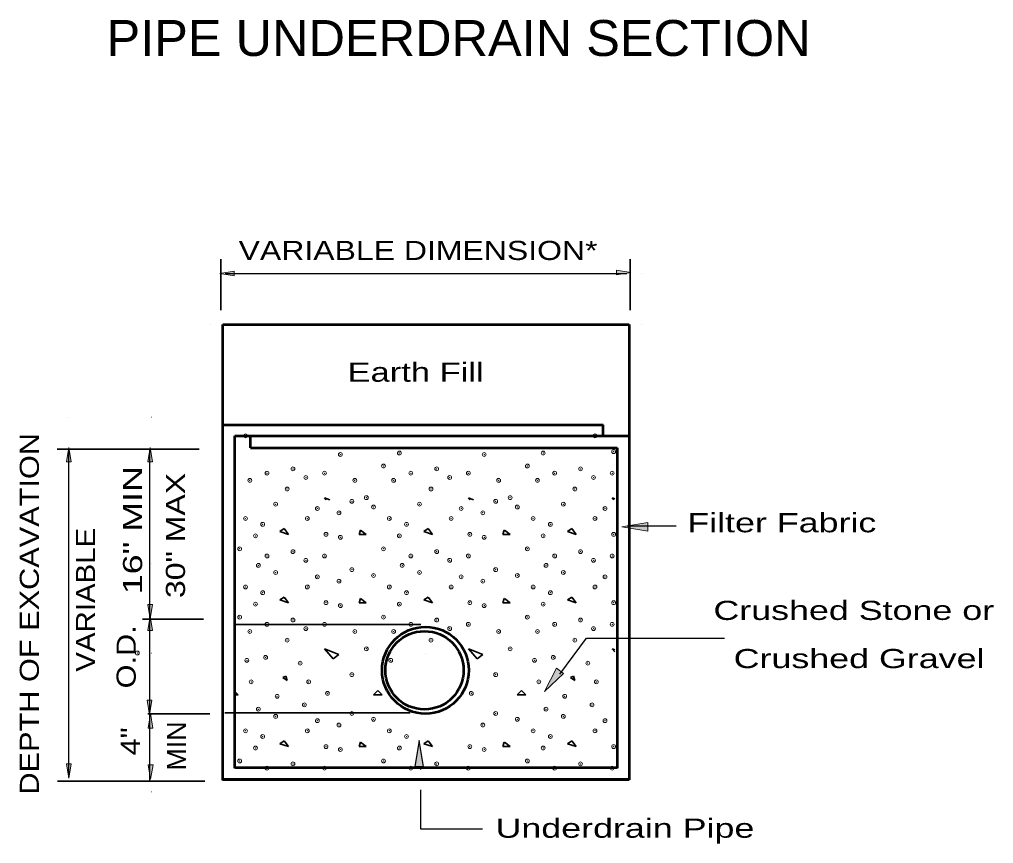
# Model space of a CAD drawing. Extents: x 36 to 71.3, y 0.3 to 22.3.
# Drawn here: x 54.2 to 60.98, y 10.65 to 16.38 of the extents above; entities that cross this region are included whole.
import ezdxf

# ---------------------------------------------------------------- set-up
doc = ezdxf.new("R2010")
doc.units = 0
doc.header["$LTSCALE"] = 0.053
doc.header["$PDMODE"] = 32
doc.header["$PDSIZE"] = 0.0265
for name, color, linetype, lineweight in [('1', 7, 'Continuous', 13), ('2', 7, 'Continuous', 13), ('4', 7, 'Continuous', 13)]:
    doc.layers.add(name, color=color, linetype=linetype, lineweight=lineweight)

msp = doc.modelspace()

# ---------------------------------------------------------------- hatches: boundary and pattern name
at = {"layer": '1'}
for points in [[(55.69842, 14.62858), (55.69842, 14.59525), (55.5985, 14.61192), (55.5985, 14.61192)], [(58.35667, 14.635), (58.35667, 14.60167), (58.45667, 14.61833), (58.45667, 14.61833)], [(54.53083, 13.30133), (54.56425, 13.30133), (54.54758, 13.40142), (54.54758, 13.40142)], [(55.09717, 13.30183), (55.1305, 13.30183), (55.11375, 13.40183), (55.11375, 13.40183)], [(55.09717, 12.3105), (55.1305, 12.3105), (55.11375, 12.2105), (55.11375, 12.2105)], [(55.09717, 12.12867), (55.1305, 12.12867), (55.11375, 12.22867), (55.11375, 12.22867)], [(54.53083, 11.20267), (54.56425, 11.20267), (54.54758, 11.10275), (54.54758, 11.10275)]]:
    msp.add_hatch(color=256, dxfattribs=at).paths.add_polyline_path(points)
at = {"layer": '2'}
for points in [[(58.57267, 12.81967), (58.57267, 12.87967), (58.39267, 12.84967), (58.39267, 12.84967)], [(57.98708, 11.83075), (57.93892, 11.86667), (57.8555, 11.70442), (57.8555, 11.70442)], [(55.09267, 11.64392), (55.126, 11.64392), (55.10925, 11.544), (55.10925, 11.544)], [(55.09992, 11.45125), (55.13325, 11.45125), (55.1165, 11.55125), (55.1165, 11.55125)], [(56.95408, 11.1845), (57.01408, 11.1845), (56.98408, 11.3645), (56.98408, 11.3645)], [(55.1, 11.19533), (55.13333, 11.19533), (55.11658, 11.09542), (55.11658, 11.09542)]]:
    msp.add_hatch(color=256, dxfattribs=at).paths.add_polyline_path(points)

# ---------------------------------------------------------------- linework, layer by layer
at = {"layer": '1', "lineweight": 35}
for p, q in [((55.60492, 14.3575), (55.60492, 14.71192)), ((58.45025, 14.3575), (58.45025, 14.71192)), ((55.45392, 13.38958), (54.46667, 13.38958)), ((56.326, 13.05267), (56.362, 13.03825)), ((56.33833, 13.03825), (56.326, 13.05267)), ((57.326, 13.05267), (57.362, 13.03825)), ((57.33833, 13.03825), (57.326, 13.05267)), ((58.33833, 13.03825), (58.326, 13.05267)), ((58.326, 13.05267), (58.34417, 13.04542)), ((56.046, 12.83742), (56.016, 12.81742)), ((56.01608, 12.81742), (56.07608, 12.79742)), ((56.076, 12.79742), (56.046, 12.83742)), ((56.576, 12.82733), (56.566, 12.79733)), ((56.61608, 12.79733), (56.57608, 12.82733)), ((57.046, 12.83742), (57.016, 12.81742)), ((57.01608, 12.81742), (57.07608, 12.79742)), ((57.076, 12.79742), (57.046, 12.83742)), ((57.576, 12.82733), (57.566, 12.79733)), ((57.61608, 12.79733), (57.57608, 12.82733)), ((58.046, 12.83742), (58.016, 12.81742)), ((58.01608, 12.81742), (58.07608, 12.79742)), ((58.076, 12.79742), (58.046, 12.83742)), ((56.56608, 12.79742), (56.61608, 12.79742)), ((57.56608, 12.79742), (57.61608, 12.79742)), ((56.046, 12.36208), (56.016, 12.34208)), ((56.01608, 12.34208), (56.07608, 12.32208)), ((56.076, 12.32208), (56.046, 12.36208)), ((56.576, 12.352), (56.566, 12.322)), ((56.61608, 12.322), (56.57608, 12.352)), ((57.046, 12.36208), (57.016, 12.34208)), ((57.01608, 12.34208), (57.07608, 12.32208)), ((57.076, 12.32208), (57.046, 12.36208)), ((57.576, 12.352), (57.566, 12.322)), ((57.61608, 12.322), (57.57608, 12.352)), ((58.046, 12.36208), (58.016, 12.34208)), ((58.01608, 12.34208), (58.07608, 12.32208)), ((58.076, 12.32208), (58.046, 12.36208)), ((56.56608, 12.32208), (56.61608, 12.32208)), ((57.56608, 12.32208), (57.61608, 12.32208)), ((56.326, 12.002), (56.426, 11.962)), ((56.386, 11.932), (56.326, 12.002)), ((57.326, 12.002), (57.426, 11.962)), ((57.386, 11.932), (57.326, 12.002)), ((58.326, 12.002), (58.34417, 11.99475)), ((58.34417, 11.98083), (58.326, 12.002)), ((56.426, 11.96208), (56.386, 11.93208)), ((57.426, 11.96208), (57.386, 11.93208)), ((56.056, 11.81208), (56.036, 11.80208)), ((56.036, 11.802), (56.066, 11.782)), ((56.06608, 11.78208), (56.05608, 11.81208)), ((58.056, 11.81208), (58.036, 11.80208)), ((58.036, 11.802), (58.066, 11.782)), ((58.06608, 11.78208), (58.05608, 11.81208)), ((55.72608, 11.682), (55.71033, 11.69775)), ((55.71033, 11.68208), (55.72608, 11.68208)), ((56.696, 11.712), (56.666, 11.682)), ((56.666, 11.68208), (56.72592, 11.68208)), ((56.72592, 11.68217), (56.69608, 11.712)), ((57.696, 11.712), (57.666, 11.682)), ((57.66608, 11.68208), (57.72608, 11.68208)), ((57.72608, 11.682), (57.69608, 11.712)), ((56.046, 11.36208), (56.016, 11.34208)), ((56.01608, 11.34208), (56.07608, 11.32208)), ((56.076, 11.32208), (56.046, 11.36208)), ((56.576, 11.352), (56.566, 11.322)), ((56.56608, 11.32208), (56.61608, 11.32208)), ((56.61608, 11.322), (56.57608, 11.352)), ((57.046, 11.36208), (57.016, 11.34208)), ((57.01608, 11.34208), (57.07608, 11.32208)), ((57.076, 11.32208), (57.046, 11.36208)), ((57.076, 11.32208), (57.046, 11.36208)), ((57.576, 11.352), (57.566, 11.322)), ((57.56608, 11.32208), (57.61608, 11.32208)), ((57.61608, 11.322), (57.57608, 11.352)), ((58.046, 11.36208), (58.016, 11.34208)), ((58.01608, 11.34208), (58.07608, 11.32208)), ((58.076, 11.32208), (58.046, 11.36208)), ((55.45667, 11.08083), (54.46942, 11.08083))]:
    msp.add_line(p, q, dxfattribs=at)
at = {"layer": '1', "lineweight": 25}
for p, q in [((55.63483, 14.61192), (58.42675, 14.61192)), ((54.54758, 11.108), (54.54758, 13.38958))]:
    msp.add_line(p, q, dxfattribs=at)
at = {"layer": '1', "lineweight": 53}
for p, q in [((55.61817, 14.2575), (58.44342, 14.2575)), ((55.61817, 11.09133), (55.61817, 14.2575)), ((58.44342, 14.2575), (58.44342, 11.09242)), ((55.61817, 13.55817), (58.26317, 13.55817)), ((58.26392, 13.48425), (58.26392, 13.5585)), ((55.7015, 11.17208), (55.7015, 13.48275)), ((55.7015, 13.48275), (58.26317, 13.48275)), ((55.81042, 13.3995), (55.81042, 13.48275)), ((55.81042, 13.48242), (58.44425, 13.48242)), ((58.44342, 13.48242), (58.44342, 11.09133)), ((55.81042, 13.39908), (58.36008, 13.39908)), ((58.36008, 13.39908), (58.36008, 11.17208)), ((58.36008, 11.17467), (55.7015, 11.17467)), ((58.44342, 11.09242), (55.61267, 11.09242)), ((58.44342, 11.09133), (55.61817, 11.09133))]:
    msp.add_line(p, q, dxfattribs=at)
at = {"layer": '1'}
for points in [[(55.69842, 14.62858), (55.69842, 14.59525), (55.5985, 14.61192), (55.5985, 14.61192)], [(58.35667, 14.635), (58.35667, 14.60167), (58.45667, 14.61833), (58.45667, 14.61833)], [(54.53083, 13.30133), (54.56425, 13.30133), (54.54758, 13.40142), (54.54758, 13.40142)], [(55.09717, 13.30183), (55.1305, 13.30183), (55.11375, 13.40183), (55.11375, 13.40183)], [(55.09717, 12.3105), (55.1305, 12.3105), (55.11375, 12.2105), (55.11375, 12.2105)], [(55.09717, 12.12867), (55.1305, 12.12867), (55.11375, 12.22867), (55.11375, 12.22867)], [(54.53083, 11.20267), (54.56425, 11.20267), (54.54758, 11.10275), (54.54758, 11.10275)]]:
    msp.add_lwpolyline(points, close=True, dxfattribs=at)
at = {"layer": '1', "lineweight": 53}
for centre, radius in [((57.0275, 11.85258), 0.30179), ((57.021, 11.85258), 0.27211)]:
    msp.add_circle(centre, radius, dxfattribs=at)
at = {"layer": '1'}
for p in [(55.77608, 13.48275), (58.20608, 13.48275), (56.436, 13.35275), (56.84608, 13.36267), (57.43608, 13.35275), (57.84608, 13.36267), (58.33608, 13.37275), (56.73608, 13.27267), (57.73608, 13.27267), (55.92608, 13.22275), (56.10608, 13.25275), (56.19608, 13.19275), (56.32608, 13.22275), (56.92608, 13.22275), (57.10608, 13.25275), (57.19608, 13.19275), (57.32608, 13.22275), (57.92608, 13.22275), (58.10608, 13.25275), (58.19608, 13.19275), (58.32608, 13.22275), (55.80608, 13.17275), (56.53608, 13.17275), (56.80608, 13.17275), (57.53608, 13.17275), (57.80608, 13.17275), (56.06608, 13.11267), (57.06608, 13.11267), (58.06608, 13.11267), (55.98608, 13.00742), (56.51608, 13.02742), (56.61608, 13.05275), (56.98608, 13.00742), (57.51608, 13.02742), (57.61608, 13.05275), (57.98608, 13.00742), (56.27608, 12.97742), (56.42608, 12.94733), (56.666, 12.98742), (57.27608, 12.97742), (57.42608, 12.94733), (57.66608, 12.98742), (58.27608, 12.97742), (55.77608, 12.90742), (55.89608, 12.86742), (56.20608, 12.90742), (56.77608, 12.90742), (56.89608, 12.86742), (57.20608, 12.90742), (57.77608, 12.90742), (57.89608, 12.86742), (58.20608, 12.90742), (55.846, 12.78733), (56.33608, 12.79742), (56.84608, 12.78733), (57.33608, 12.79742), (57.84608, 12.78733), (58.33608, 12.79742), (56.436, 12.77742), (57.43608, 12.77742), (55.73608, 12.69733), (56.10608, 12.67742), (56.73608, 12.69733), (57.10608, 12.67742), (57.73608, 12.69733), (58.10608, 12.67742), (55.92608, 12.64742), (56.19608, 12.61742), (56.32608, 12.64742), (56.92608, 12.64742), (57.19608, 12.61742), (57.32608, 12.64742), (57.92608, 12.64742), (58.19608, 12.61742), (58.32608, 12.64742), (55.86608, 12.58208), (55.98608, 12.53208), (56.51608, 12.55208), (56.86608, 12.58208), (56.98608, 12.53208), (57.51608, 12.55208), (57.86608, 12.58208), (57.98608, 12.53208), (56.27608, 12.50208), (56.42608, 12.472), (56.666, 12.51208), (57.27608, 12.50208), (57.42608, 12.472), (57.66608, 12.51208), (58.27608, 12.50208), (55.77608, 12.43208), (55.89608, 12.39208), (56.20608, 12.43208), (56.77608, 12.43208), (56.89608, 12.39208), (57.20608, 12.43208), (57.77608, 12.43208), (57.89608, 12.39208), (58.20608, 12.43208), (56.33608, 12.32208), (57.33608, 12.32208), (58.33608, 12.32208), (55.846, 12.312), (56.436, 12.30208), (56.84608, 12.312), (57.43608, 12.30208), (57.84608, 12.312), (55.73608, 12.222), (56.10608, 12.20208), (56.73608, 12.222), (57.10608, 12.20208), (57.73608, 12.222), (58.10608, 12.20208), (55.80608, 12.12208), (55.92608, 12.17208), (56.19608, 12.14208), (56.32608, 12.17208), (56.53608, 12.12208), (56.80608, 12.12208), (56.92608, 12.17208), (57.19608, 12.14208), (57.32608, 12.17208), (57.53608, 12.12208), (57.80608, 12.12208), (57.92608, 12.17208), (58.19608, 12.14208), (58.32608, 12.17208), (56.06608, 12.062), (57.06608, 12.062), (58.06608, 12.062), (56.61608, 12.00208), (57.61608, 12.00208), (55.02383, 11.97267), (55.78608, 11.92208), (55.916, 11.94208), (56.78608, 11.92208), (57.78608, 11.92208), (57.91608, 11.94208), (56.15608, 11.90208), (58.15608, 11.90208), (55.81608, 11.77208), (56.21608, 11.77208), (56.51608, 11.82208), (57.51608, 11.82208), (57.81608, 11.77208), (58.21608, 11.77208), (55.99608, 11.67208), (56.346, 11.69208), (57.34608, 11.69208), (57.99608, 11.67208), (55.86608, 11.58208), (56.186, 11.61208), (57.86608, 11.58208), (58.18608, 11.61208), (55.98608, 11.53208), (56.27608, 11.50208), (56.51608, 11.55208), (56.666, 11.51208), (57.51608, 11.55208), (57.66608, 11.51208), (57.98608, 11.53208), (58.27608, 11.50208), (55.77608, 11.43208), (56.20608, 11.43208), (56.42608, 11.472), (56.77608, 11.43208), (57.42608, 11.472), (57.77608, 11.43208), (58.20608, 11.43208), (55.89608, 11.39208), (56.89608, 11.39208), (57.89608, 11.39208), (55.846, 11.312), (56.33608, 11.32208), (56.436, 11.30208), (56.84608, 11.312), (57.33608, 11.32208), (57.43608, 11.30208), (57.84608, 11.312), (58.33608, 11.32208), (55.73608, 11.222), (55.92608, 11.17208), (56.10608, 11.20208), (56.32608, 11.17208), (56.73608, 11.222), (56.92608, 11.17208), (57.10608, 11.20208), (57.32608, 11.17208), (57.73608, 11.222), (57.92608, 11.17208), (58.10608, 11.20208), (58.32608, 11.17208)]:
    msp.add_point(p, dxfattribs=at)
at = {"layer": '2'}
for p, q in [((55.12392, 13.61275), (55.124, 13.61275)), ((55.12392, 11.97267), (55.124, 11.97267)), ((55.12392, 11.008), (55.124, 11.008))]:
    msp.add_line(p, q, dxfattribs=at)
at = {"layer": '2', "lineweight": 25}
for p, q in [((55.10933, 13.39267), (55.10933, 11.08158)), ((58.43008, 12.85717), (58.77133, 12.85717)), ((57.96292, 11.82633), (58.14817, 12.075)), ((58.14817, 12.075), (59.1075, 12.075)), ((58.52758, 12.075), (59.1075, 12.075)), ((56.993, 11.17558), (56.993, 11.162)), ((56.993, 11.02025), (56.993, 10.74917)), ((56.993, 10.74917), (57.42383, 10.74917))]:
    msp.add_line(p, q, dxfattribs=at)
at = {"layer": '2', "lineweight": 35}
for p, q in [((55.48325, 12.2075), (55.06058, 12.2075)), ((56.99483, 12.16975), (55.69742, 12.16975)), ((57.0275, 11.97267), (57.02758, 11.97267)), ((55.52775, 11.55), (55.09625, 11.55)), ((56.92117, 11.55725), (55.6325, 11.55725)), ((57.0275, 11.36908), (57.02758, 11.36908)), ((57.0275, 11.36908), (57.02758, 11.36908)), ((55.49308, 11.08083), (55.08217, 11.08083))]:
    msp.add_line(p, q, dxfattribs=at)
at = {"layer": '2'}
for points in [[(58.57267, 12.81967), (58.57267, 12.87967), (58.39267, 12.84967), (58.39267, 12.84967)], [(57.98708, 11.83075), (57.93892, 11.86667), (57.8555, 11.70442), (57.8555, 11.70442)], [(55.09267, 11.64392), (55.126, 11.64392), (55.10925, 11.544), (55.10925, 11.544)], [(55.09992, 11.45125), (55.13325, 11.45125), (55.1165, 11.55125), (55.1165, 11.55125)], [(55.1, 11.19533), (55.13333, 11.19533), (55.11658, 11.09542), (55.11658, 11.09542)]]:
    msp.add_lwpolyline(points, close=True, dxfattribs=at)
at = {"layer": '2', "lineweight": 25}
msp.add_lwpolyline([(56.95408, 11.1845), (57.01408, 11.1845), (56.98408, 11.3645), (56.98408, 11.3645)], close=True, dxfattribs=at)
at = {"layer": '4'}
for p, q in [((58.52675, 14.61192), (58.52683, 14.61192)), ((55.53483, 14.2575), (55.53492, 14.2575)), ((58.52675, 14.2575), (58.52683, 14.2575)), ((54.54758, 13.61275), (54.54767, 13.61275)), ((55.12383, 12.59358), (55.12392, 12.59358)), ((55.12383, 11.97267), (55.12392, 11.97267))]:
    msp.add_line(p, q, dxfattribs=at)

# ---------------------------------------------------------------- texts
at = {"layer": '1', "width": 1.25}
msp.add_text('VARIABLE DIMENSION*', height=0.133, dxfattribs=at).set_placement((55.72842, 14.70508))
at = {"layer": '1'}
for s, width, p in [('DEPTH OF EXCAVATION', 1.2, (54.33992, 10.98825)), ('16" MIN', 1.4, (55.05767, 12.38133))]:
    msp.add_text(s, height=0.133, rotation=90, dxfattribs=dict(at, width=width)).set_placement(p)
at = {"layer": '2'}
for s, height, width, p in [('PIPE UNDERDRAIN SECTION', 0.25, 1.05, (54.81008, 16.12367)), ('Earth Fill', 0.133, 1.35, (56.48575, 13.85875)), ('Filter Fabric', 0.133, 1.4, (58.848, 12.812)), ('Crushed Stone or', 0.133, 1.4, (59.02975, 12.20258)), ('Crushed Gravel', 0.133, 1.4, (59.1705, 11.86767)), ('Underdrain Pipe', 0.133, 1.4, (57.51475, 10.68825))]:
    msp.add_text(s, height=height, dxfattribs=dict(at, width=width)).set_placement(p)
for s, width, p in [('30" MAX', 1.25, (55.35575, 12.35492)), ('VARIABLE', 1.15, (54.73067, 11.84283)), ('O.D.', 1.2, (55.01317, 11.72667)), ('4"', 1.2, (55.04258, 11.26092)), ('MIN', 1.05, (55.36358, 11.15533))]:
    msp.add_text(s, height=0.133, rotation=90, dxfattribs=dict(at, width=width)).set_placement(p)

doc.saveas('drawing.dxf')
